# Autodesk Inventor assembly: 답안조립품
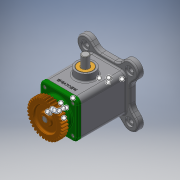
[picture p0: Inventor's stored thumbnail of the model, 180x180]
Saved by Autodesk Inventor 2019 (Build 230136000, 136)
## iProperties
Created: 2021-01
Part Number: 답안조립품
Material: 일반
Document SubType Name: Assembly
Designer: 3DPRO15
Author: 3DPRO15
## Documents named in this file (11)
- C:\Users\3DPRO15\Desktop\710114V1007\답안조립품.iam
- C:\Users\3DPRO15\Desktop\710114V1007\본체.ipt
- C:\Users\3DPRO15\Desktop\710114V1007\베어링 6203.ipt
- C:\Users\3DPRO15\Desktop\710114V1007\볼트 M4.ipt
- C:\Users\3DPRO15\Desktop\710114V1007\부시.ipt
- C:\Users\3DPRO15\Desktop\710114V1007\스퍼기어.ipt
- C:\Users\3DPRO15\Desktop\710114V1007\슬라이더.ipt
- C:\Users\3DPRO15\Desktop\710114V1007\오일 실.ipt
- C:\Users\3DPRO15\Desktop\710114V1007\커버.ipt
- C:\Users\3DPRO15\Desktop\710114V1007\키 4 x 4 x 14.ipt
- C:\Users\3DPRO15\Desktop\710114V1007\편심축.ipt
